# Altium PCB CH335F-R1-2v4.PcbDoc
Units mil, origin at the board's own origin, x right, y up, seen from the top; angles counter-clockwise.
Board outline 3110.24 x 866.14 mil, 2 copper layers (Top Layer, Bottom Layer); 18 components, 20 nets, 111 pads, 301 vias.
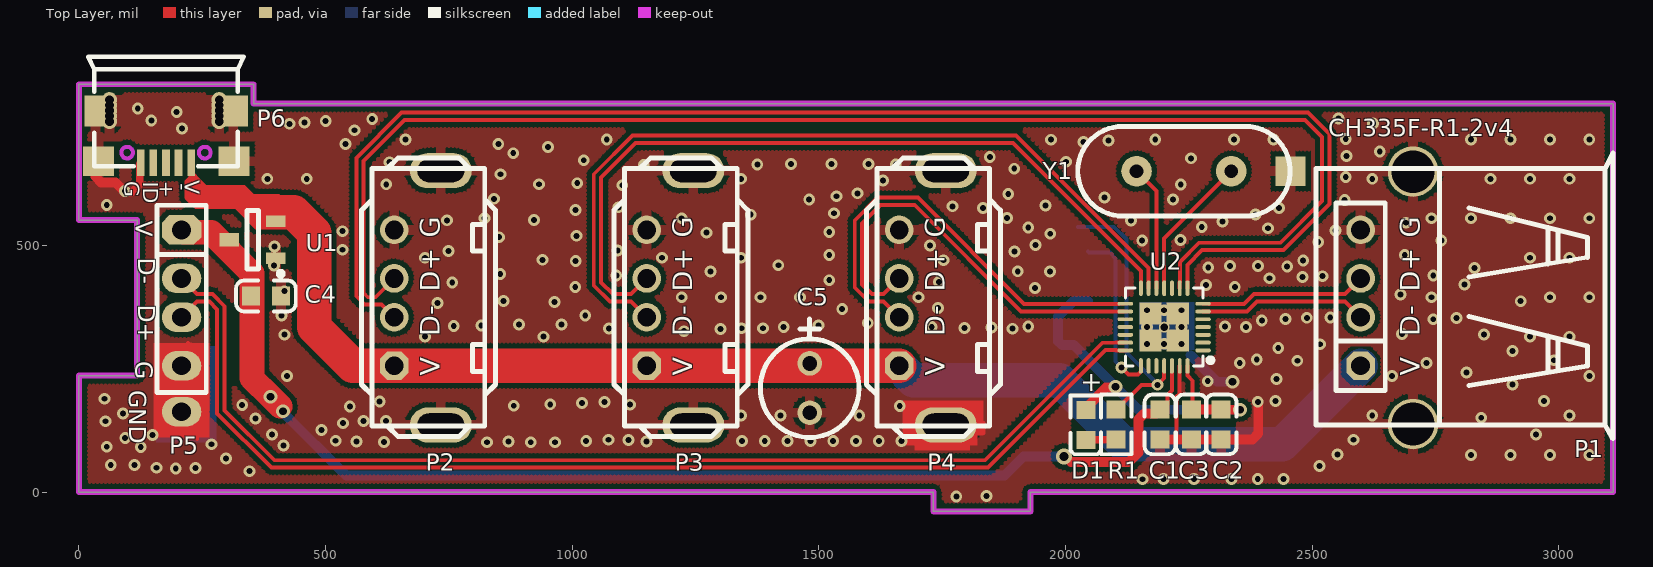
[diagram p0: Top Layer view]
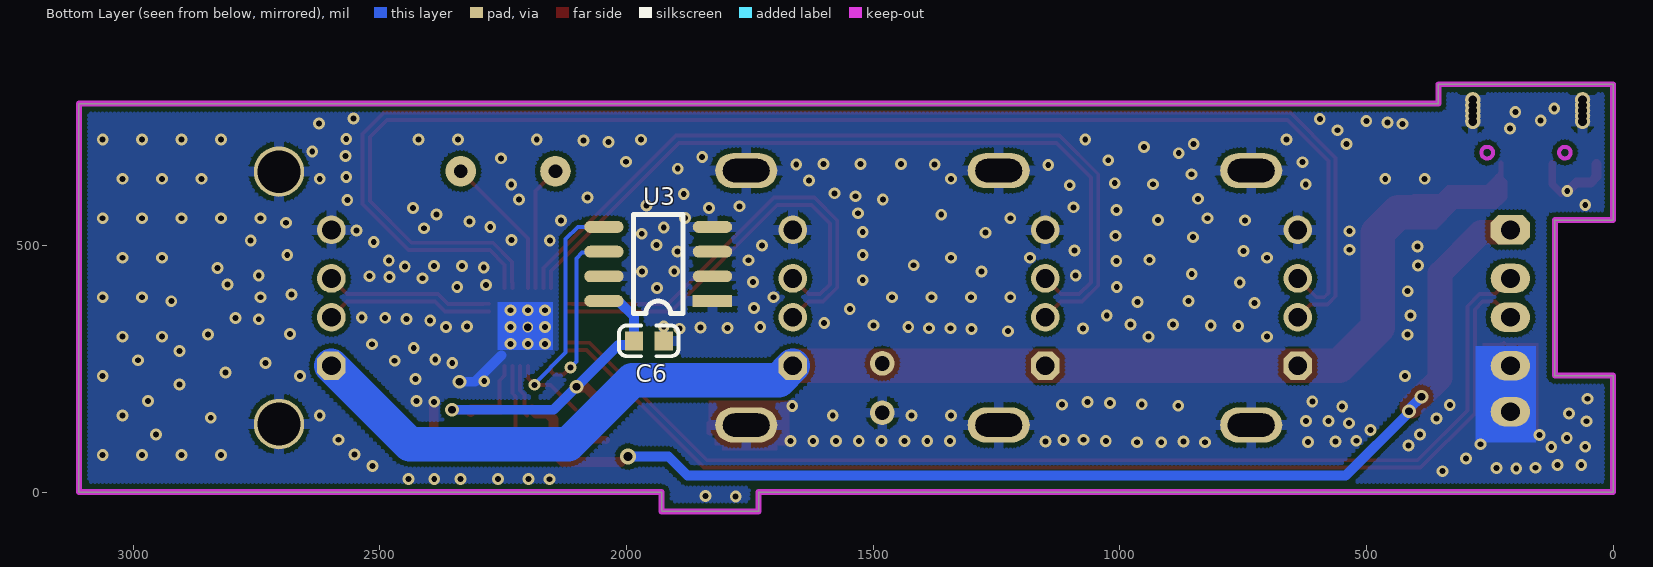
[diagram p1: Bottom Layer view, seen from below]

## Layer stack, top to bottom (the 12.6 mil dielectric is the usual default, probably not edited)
Top Solder: solder mask 0.4, Solder Resist, Dk 3.5
Top Layer: signal copper 1.4
Dielectric 1: dielectric 12.6, FR-4, Dk 4.8
Bottom Layer: signal copper 1.4
Bottom Solder: solder mask 0.4, Solder Resist, Dk 3.5

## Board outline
0,0 0,236.22 118.11,236.22 118.11,551.18 0,551.18 0,826.77 354.33,826.77 354.33,787.4 3110.24,787.4 3110.24,0 1929.13,0 1929.13,-39.37 1732.28,-39.37 1732.28,0

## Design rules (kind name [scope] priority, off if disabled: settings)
Clearance Clearance_1 [InPolygon] p1: gap=10 ignorepadtopadclearanceinfootprint=FALSE
Clearance [All] p2: gap=6 ignorepadtopadclearanceinfootprint=FALSE except(8: Arc-Via Track-Via SMDPad-Via THPad-Via Via-Via Via-Fill Via-Poly Via-Region Via-Hole)
ComponentClearance [All] p1 off: gap=10 collisioncheckmode=3 verticalgap=10 showdistances=FALSE
DiffPairsRouting [All] p1: maxlimit=10 minlimit=7 mostfreqgap=8 toplayer_minwidth=6 toplayer_maxwidth=15 toplayer_prefwidth=8 bottomlayer_minwidth=6 bottomlayer_maxwidth=15 bottomlayer_prefwidth=8 maxuncoupledlength=500
MinimumSolderMaskSliver [All] p1 off: minsoldermaskwidth=10
PolygonConnect PolygonConnect_1 [IsVia] p1: connectstyle=Direct reliefconductorwidth=10 reliefentries=4 polygonreliefangle="90 Angle" airgapwidth=10
PolygonConnect [All] p2: connectstyle=Relief reliefconductorwidth=20 reliefentries=4 polygonreliefangle="90 Angle" airgapwidth=10
RoutingVias [All] p1: holewidth=16 width=28 viastyle="Through Hole" minholewidth=12 minwidth=24 maxholewidth=28 maxwidth=50
SilkToSilkClearance [All] p1 off: silktosilkclearance=10
SilkToSolderMaskClearance [IsPad] p1 off: minsilkscreentomaskgap=10 clearancetoexposedcopper=TRUE
SolderMaskExpansion [All] p1: expansion=4 istentingtop=FALSE
Width [All] p1: maxlimit=100 minlimit=6 preferedwidth=10
25 further rules are at their usual default settings.

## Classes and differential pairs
differential pair UD: +UD_p -UD_n
differential pair UD4: +UD4_p -UD4_n
differential pair UD3: +UD3_p -UD3_n
differential pair UD2: +UD2_p -UD2_n
differential pair UD1: +UD1_p -UD1_n

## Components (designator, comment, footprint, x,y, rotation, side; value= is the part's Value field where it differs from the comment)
C1 "1uF" 0603_C 2191.7,167.36 r270 top
C2 "10uF" 0603_C 2315.79,167.36 r270 top
C3 "0.1uF" 0603_C 2255.33,167.36 r270 top
C4 "10uF" 0603_C 349,397.5 r0 top
C5 "220uF" CD0.1 1481.53,260.82 r270 top
C6 "NC(1uF)" 0603_C 1924.53,306.51 r0 bottom
D1 "LED" 0603+ 2041.27,165.98 r270 top
P1 "USB" USBAF#1 2598.25,255.91 r90 top
P2 "USB" USB2.0-A-F-TH_4P-V_13.7mm 639.21,255.91 r180 top
P3 "USB" USB2.0-A-F-TH_4P-V_13.7mm 1151.02,255.91 r180 top
P4 "USB" USB2.0-A-F-TH_4P-V_13.7mm 1662.83,255.91 r180 top
P5 "USB" USBAF#2 208.21,531.5 r270 top
P6 "PowerSupply" USBMICROB-02-GXPX-A1T2 227.66,667.45 r180 top
R1 "1K" 0603_R 2102.92,137.04 r270 top
U1 "CH213K" SOT-23-3 399.31,474.12 r90 top
U2 "CH335F" QFN28_4X4 2200.14,334.5 r90 top
U3 "NC(24C02)" SOIC-8_150mil 1825.82,387.4 r90 bottom
Y1 "12M" XT_AT49 2336.23,650.53 r90 top

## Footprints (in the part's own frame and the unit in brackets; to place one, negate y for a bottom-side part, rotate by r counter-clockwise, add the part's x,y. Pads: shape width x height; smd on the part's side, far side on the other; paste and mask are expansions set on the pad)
0603+ [mm]
  rect 0.93x0.98 smd: 1(0,0) 2(1.54,0)
  silkscreen extent -0.76,-0.79 2.27,0.79
0603_C [mm]
  rect 0.93x0.98 smd: 1(0,0) 2(1.54,0)
  silkscreen extent -0.76,-0.79 2.31,0.79
0603_R [mm]
  rect 0.93x0.98 smd: 1(-0.77,0) 2(0.77,0)
  silkscreen extent -1.53,-0.79 1.54,0.79
CD0.1 [mil]
  round 50 hole 30: 1(0,0) 2(100,0)
  silkscreen extent -90,-100 150,100
QFN28_4X4 [mm]
  rect 1.143x1.143 smd mask+0: 0(-0.699,-0.699) 0(-0.699,0.698) 0(0.699,-0.699) 0(0.699,0.698)
  round 0.559 hole 0.381 mask+0.051: 0(0,0)
  oval 0.2x0.8 smd mask+0.051: 1(-1.2,-2) 2(-0.8,-2) 3(-0.4,-2) 4(0,-2) 5(0.4,-2) 6(0.8,-2) 7(1.2,-2) 15(1.2,2) 16(0.8,2) 17(0.4,2) 18(0,2) 19(-0.4,2) 20(-0.8,2) 21(-1.2,2)
  oval 0.8x0.2 smd mask+0.051: 8(2,-1.2) 9(2,-0.8) 10(2,-0.4) 11(2,0) 12(2,0.4) 13(2,0.8) 14(2,1.2) 22(-2,1.2) 23(-2,0.8) 24(-2,0.4) 25(-2,0) 26(-2,-0.4) 27(-2,-0.8) 28(-2,-1.2)
  silkscreen extent -2,-2.51 2,2
SOIC-8_150mil [mil]
  rect 24x80 smd: 1(0,0)
  oval 24x80 smd: 2(50,0) 3(100,0) 4(150,0) 5(150,220) 6(100,220) 7(50,220) 8(0,220)
  silkscreen extent -25,60 175,160
SOT-23-3 [mm] "SOT-23-3"
  rect 0.6x1 smd: 1(0,0) 2(1.9,0)
  rect 0.7x1 smd: 3(0.95,2.4)
  silkscreen extent -0.93,-0.38 2.45,1.49
USB2.0-A-F-TH_4P-V_13.7mm [mm]
  oval 3.2x1.8 hole 1.2 slot 2.4 at 0 deg: 0(-2.4,3.05) 0(-2.4,-10.05)
  oct 1.473x1.473 hole 0.965: 1(0,0)
  round 1.473 hole 0.965: 2(0,-2.5) 3(0,-4.5) 4(0,-7)
  silkscreen extent -5.21,-10.71 1.69,3.65
USBAF#1 [mm]
  round 2.6 hole 2.2: 0(-3,-2.7) 0(10,-2.7)
  oct 1.473x1.473 hole 0.965: 1(0,0)
  round 1.473 hole 0.965: 2(2.5,0) 3(4.5,0) 4(7,0)
  silkscreen extent -3.75,-12.99 10.95,2.29
USBAF#2 [mm]
  oct 1.524x2.032 hole 0.965: 1(0,0)
  oval 1.524x2.032 hole 0.965: 2(2.5,0) 3(4.5,0) 4(7,0)
  silkscreen extent -1.27,-1.27 8.38,1.27
USBMICROB-02-GXPX-A1T2 [mm]
  rect 1.6x1.5 smd: 0(-2.203,-0.083) 0(4.769,-0.083)
  rect 1.5x1.6 smd: 0(-2.167,-2.675)
  round 0.8 hole 0.45: 0(-1.442,-2.134) 0(-1.442,-3.243) 0(-1.442,-2.966) 0(-1.442,-2.689) 0(-1.442,-2.411) 0(4.208,-2.689) 0(4.208,-2.411) 0(4.208,-2.134) 0(4.208,-3.243) 0(4.208,-2.966)
  rect 1.1x1.6 smd: 0(4.933,-2.675)
  rect 0.4x1.35 smd mask+0.051: 1(0,0) 2(0.65,0) 3(1.3,0) 4(1.95,0) 5(2.6,0)
  Keep-Out Layer circle w0.203: c3.3,-0.525 r0.3
  Keep-Out Layer circle w0.203: c-0.7,-0.525 r0.3
  silkscreen extent -2.7,-5.46 5.3,0.17
XT_AT49 [mil]
  rect 60x60 smd: 0(0.03,-119.99)
  round 62 hole 28: 1(0,0) 2(0,192.13)
  silkscreen extent -91,-119 91,311

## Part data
C1 C2 C3 C4 C5 C6: library part CAP, "Capacitor"
D1: "Typical INFRARED GaAs LED"
P1 P2 P3 P4 P5: "USB Port"
P6: library part MicroUSB, "MicroUSB Port"
R1: library part RES
U1: "Ideal Diode 5V*1A"
U2: "4 ports High-Speed USB MTT Hub with 4 over current detect & power control"
U3: library part 24C01
Y1: library part XTAL, "Crystal Oscillator"

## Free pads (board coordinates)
  oval 80x60 hole 38: ""(208.21,162.81)

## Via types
v1: diameter 24, hole 12, Top Layer to Bottom Layer, tented both sides, 295 vias
v2: diameter 28, hole 16, Top Layer to Bottom Layer, tented both sides, 5 vias
v3: diameter 32, hole 18, Top Layer to Bottom Layer, tented both sides, 1 vias

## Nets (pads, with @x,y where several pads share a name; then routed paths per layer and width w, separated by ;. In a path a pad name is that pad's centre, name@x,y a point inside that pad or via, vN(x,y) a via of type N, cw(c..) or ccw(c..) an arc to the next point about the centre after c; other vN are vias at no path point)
3V3: C2.1 C3.1 C6.2 D1.1 U2.28 U3.8 | length 826.5
  Top Layer w8: U2.28 2247.39,235.98 2257.75,225.62 C3.1@2257.75,167.36
  Top Layer w20: D1.1 2042.26,165.98 2050.57,174.28 2050.57,179.46 2065.22,194.12 2065.22,195.06 2082.1,211.95 2099.74,211.95 v2(2101.27,213.48) ; C3.1 2257.75,167.36 C2.1 ; C2.1@2315.79,162.1 2320.59,166.9 v2(2353.6,166.9)
  Bottom Layer w20: C6.2@1985.16,305.53 C6.2@1985.16,306.39 ; U3.8 2016.74,387.4 1985.16,355.82 C6.2 C6.2@1985.16,306.39 ; v2(2353.6,166.9) 2147.92,166.9 2016.75,298.08 1993.46,298.08 C6.2@1985.16,306.39
5V: C1.1 C4.1 P5.1 U1.3 U2.26 | length 2567.1
  Top Layer w8: C1.1@2201.91,155.57 2206.99,160.65 2206.99,196.73 2215.89,205.63 U2.26
  Top Layer w20: v2(413.82,163.9) 416.27,163.9 v2@422.95,170.59 ; v3(1997,72) 2000.25,72 2011.02,61.23 2128.8,61.23 2148.07,80.5 2148.07,147.53 2159.78,159.24 2183.59,159.24 C1.1
  Top Layer w50: P5.1 212.86,526.85 267.86,526.85 350.86,443.86 350.86,231.09 v2(388.71,193.23) v2@407.93,174.01
  Bottom Layer w20: v2(388.71,193.23) 413.82,168.12 v2(413.82,163.9) 413.82,161.47 541.94,33.35 1876.39,33.35 1915.04,72 v3(1997,72)
GND: C1.2 C2.2 C3.2 C4.2 C5.2 C6.1 P1.0 P1.4 P2.0 P2.4 P3.0 P3.4 P4.0 P4.4 P5.4 P6.0 P6.5 pad. U1.1 U2.0 U2.27 U3.1 U3.2 U3.3 U3.4 U3.7 Y1.0 | length 1560
  Top Layer w8: 220.81,208.41 220.81,302.53 ; 222,112.53 222,206.65 ; 225,112.53 225,206.65 ; 227.09,204.87 227.09,299 ; 230,111.08 230,205.21 ; 233,204.17 233,298.3 ; 234,111.08 234,205.21 ; 240,107.99 240,295.21 ; 1834.11,119.74 1834.11,140.29 ; 2225.32,106.73 2225.32,193.95 2231.64,200.27 U2.27
  Top Layer w15: 104.84,605.5 123.71,624.36 P6.5@123.71,665.85
  Top Layer w20: P6.0@33.46,665 33.46,639.41 45.12,627.76 74.35,627.76 91.94,610.17 v1(93.02,610.17) ; C1.2 2225.32,106.73 C3.2 C2.2 2379.08,106.73 2390.79,118.44 2390.79,181.02 2389.91,181.9 v1(2389.91,182.98)
  Bottom Layer w20: 2253.43,277.44 2307.24,223.63 v2(2338.61,223.63)
  other v1: 1778.73,-8.71 1840.22,-8.03 2156.11,26 2198.52,26.3 2260.61,26.3 2336.5,26.3 2389.86,26.3 2441.72,26.3 345.77,42.29 196.36,47.86 157.58,49.29 236.59,48.81 2514.7,52.91 64.67,55.04 112.56,54.56 298,68.06 2822,75 2902,75 2982,75 3062,75 2551.51,75.81 125.49,91.43 56.53,91.91 414.85,94.07 269.09,96.97 618.87,101.5 827.57,100.98 916.07,100.98 965.42,100.98 563.05,102.8 870.97,102.68 1150.93,102.68 1344.12,103.19 1390.38,103.19 1436.63,103.19 1482.89,103.19 1529.14,103.19 1575.4,103.19 1621.65,103.19 1667.91,103.19 520.64,104.1 1028.39,103.53 1114.34,105.23 1073.49,106.08 2584.23,106.08 93.89,109.63 149.43,115.38 391.59,116.41 2953.66,116.98 491.94,125.77 535.35,139.58 54.14,143.63 576.89,143.91 622.77,143.91 357.77,148.98 2842.89,150.73 1342,155 1422,155 1582,155 2622,155 3022,155 89.58,159.43 549.2,173.34 1664.05,174.13 881.63,174.96 331.09,176.59 1117.55,177.16 955.63,177.89 1020.11,180.82 1065.53,182.28 609.78,183.72 2970.04,184.47 2426.11,184.58 51.74,189.12 2906.47,218.22 2288.39,224.78 2427.67,229.49 422,235 2662,235 3062,235 2813.04,242.58 2353.32,261.95 2732.05,261.79 2470.02,266.19 2990.27,267.24 2387.72,269 2906.47,285.71 2431.43,292.07 2516.13,299.6 2165.14,300.5 2200.14,300.5 2235.14,300.5 702,315 942,315 2942,315 3022,315 417.14,319.02 2848.67,319.45 2681.97,320.55 1226.76,326.1 1300.83,330.59 1892.62,331.18 1074.39,331.87 1343.48,332.09 1386.87,332.09 1795.48,332.6 1428.77,334.33 1729.02,334.29 1849.9,333.65 2366.03,334.42 2165.14,334.5 2235.14,334.5 2323.68,335.36 1924.53,335.8 760.01,336.88 815.69,337.61 1499.1,338.08 891.89,339.81 978.34,339.81 1599.31,342.91 2398.02,347.59 2745.54,350.41 2446.02,350.89 2489.31,353.24 2792.74,353.2 2536.83,353.71 410.85,357.83 1026.45,358.11 2165.14,368.5 2200.14,368.5 2235.14,368.5 1547.41,370.82 1741.77,372.97 727.04,383.04 964.42,385.23 861.12,387.43 2922.84,386.94 1222,395 1302,395 1382,395 1462,395 1702,395 2742,395 2982,395 3062,395 2679.08,400.49 416.43,407.17 1938.12,413.6 1006.25,415.39 2343.32,415.81 2284.92,419.52 2809.11,420.69 756.97,424.97 1743.53,425.98 1521.18,429.51 2413.32,433.43 2480.53,435.75 2521.32,437.6 1089.52,439.16 2745.54,439.02 854.15,442.08 1280.14,447.3 1968.35,447.08 1903.25,447.54 2829.34,454.43 2289.55,455.22 2333.59,458 2390.61,458 2449.47,457.53 395.86,459.26 1417.86,459.82 1007.16,468.13 2481.92,469.12 1752.65,469.86 939.67,470.84 702,475 1182,475 1342,475 2942,475 3022,475 2687.75,480.44 1521.18,480.68 1896.74,487.53 749.2,488.72 1092.19,489.51 534.29,491.3 396.6,497.91 1725.48,499.88 1939.05,500.55 2512.51,507.13 2155.54,509.82 2761.91,510.3 2233.08,510.98 851.82,516.71 1009,519.49 1969.16,523.57 1272.17,525.84 1521.18,527.32 534.29,528.86 2547.29,530.47 2410.57,534.75 1924.64,536.35 2276.34,537.4 2690.64,545.94 2318.33,548.57 746.09,550.91 2133.17,550.63 922.56,551.69 822,555 1222,555 1881.66,555.45 2742,555 2822,555 2902,555 2982,555 3062,555 1362.09,562.26 2385.45,562.67 1530.66,565.24 1006.71,571.47 1832.96,575.82 2433.11,576.09 1093.71,577.24 1770.67,579.29 1959.21,580.79 56.52,582.14 2566.1,591.77 1480.46,592.99 2217.74,593.2 841.71,594.45 2078.97,596.86 1535.62,599.64 1883.96,604.43 1578.21,605.62 1101.53,621.94 623.08,623.85 932.67,623.99 2233.75,623.56 1010.25,626.12 1629.84,631.7 382,635 462,635 1342,635 2622,635 2862,635 2942,635 3022,635 2568.15,638.86 854.93,644.21 1896.17,655.57 1145.12,662.73 1375.3,663.89 1655.97,663.89 1443.81,664.72 1525.54,664.72 1600.66,664.72 629.57,668.76 2001.3,669.58 1023.41,672.66 2254.17,676.55 1846.66,679.25 2569.68,681.35 880.58,686.96 2637.09,690.68 951.33,699.4 540.34,705.78 850.26,705.62 2036.88,709.51 2087.31,712.53 1970.83,714.32 662,715 1070.19,714.85 2182,715 2342,715 2422,715 2822,715 2902,715 2982,715 3062,715 2568.15,715.65 559.03,733.42 209.17,737.14 426.68,746.52 2623.79,747.43 457.39,749.48 500.31,752.44 146.87,753.14 594.56,756.21 2553.53,757.46 198.29,770.28 119.32,777.75
NetD1_2: D1.2 R1.2 | length 62.2
  Top Layer w15: D1.2 2041.96,106.04 2102.23,106.04 R1.2
RST: U2.17
SCL: U2.22 U3.6 | length 350.7
  Top Layer w8: v1@2111.21,254.86 2127.84,238.23 2147.05,238.23 2152.9,244.08 U2.22
  Bottom Layer w8: U3.6 2047.63,485.58 2089.95,485.58 2101.81,473.72 2101.81,264.87 2113.55,253.13 v1(2113.55,252.19)
SDA: R1.1 U2.25 U3.5 | length 578.6
  Top Layer w8: R1.1 2103.91,167.36 2153.95,217.4 v1(2186.86,217.4) 2200.14,230.68 U2.25
  Bottom Layer w8: U3.5@2025.13,537.4 2098.73,537.4 2123.43,512.69 2123.43,282.72 2186.86,219.29 v1(2186.86,217.4)
UD1_n: P1.2 U2.6 | length 340.9
  Top Layer w8: U2.6 2290.57,366 2290.94,366.37 2368.17,366.37 2388,386.2 2566.38,386.2 P1.2
UD1_p: P1.3 U2.7 | length 340.9
  Top Layer w8: U2.7 2290.57,381.75 2290.94,381.37 2361.96,381.37 2381.79,401.2 2566.38,401.2 P1.3
UD2_n: P2.2 U2.8 | length 2932.6
  Top Layer w8: P2.2 639.1,354.33 613.48,379.95 579.38,379.95 562.42,396.91 562.42,677.61 654.21,769.4 2491.57,769.4 2535.17,725.8 2535.17,583.83 2441.75,490.41 2276.83,490.41 2247.01,460.59 2247.01,425.3 2247.39,424.93 U2.8
UD2_p: P2.3 U2.9 | length 2863.3
  Top Layer w8: P2.3 601.09,394.95 585.59,394.95 577.42,403.13 577.42,671.4 660.42,754.4 2485.36,754.4 2520.17,719.59 2520.17,590.05 2435.54,505.41 2270.62,505.41 2232.01,466.81 2232.01,425.3 2231.64,424.93 U2.9
UD3_n: P3.2 U2.13 | length 1668.6
  Top Layer w8: P3.2 1119.15,386.2 1076.47,386.2 1043.71,418.96 1043.71,644.31 1121.89,722.5 1899.96,722.5 2168.27,454.18 2168.27,425.3 2168.65,424.93 U2.13
UD3_p: P3.3 U2.14 | length 1594.1
  Top Layer w8: P3.3 1119.15,401.2 1082.69,401.2 1058.71,425.18 1058.71,638.1 1128.11,707.5 1893.75,707.5 2153.27,447.97 2153.27,425.3 2152.9,424.93 U2.14
UD4_n: P4.2 U2.15 | length 907.9
  Top Layer w8: P4.2 1630.96,386.2 1601.41,386.2 1572.91,414.7 1572.91,550.65 1619.08,596.82 1700.64,596.82 1916.09,381.37 2109.34,381.37 2109.72,381.75 U2.15
UD4_p: P4.3 U2.16 | length 858.2
  Top Layer w8: P4.3 1630.96,401.2 1607.62,401.2 1587.91,420.92 1587.91,544.44 1625.29,581.82 1694.43,581.82 1909.87,366.37 2109.34,366.37 2109.72,366 U2.16
UD_n: P5.2 U2.20 | length 2288.9
  Top Layer w8: P5.2 208.21,432.1 239.11,401.2 270.83,401.2 295.32,376.71 295.32,165.72 396.59,64.44 1837.19,64.44 2075.38,302.63 2102.43,302.63 2102.74,302.95 2121.34,302.95 U2.20
UD_p: P5.3 U2.21 | length 2288.9
  Top Layer w8: P5.3 208.21,355.3 239.11,386.2 264.62,386.2 280.32,370.5 280.32,159.5 390.38,49.44 1843.4,49.44 2081.6,287.63 2102.43,287.63 2102.74,287.32 2121.34,287.32 U2.21
VBUS: C5.1 P1.1 P2.1 P3.1 P4.1 P6.1 U1.2 | length 3173.9
  Top Layer w10: 247.13,591.38 252.13,591.38 ; 252.85,603.63 251.45,605.02 ; 252.85,608.63 252.85,605.02 ; 254.37,584.14 259.37,584.14 ; 267.21,605.02 262.21,605.02 ; 276.12,579.63 263.88,579.63 ; 219.15,602.21 241.73,579.63 ; 219.15,602.21 219.15,629.22 226.76,636.83 226.76,666.54 P6.1 P6.1@227.66,646.78 ; 219.15,602.21 219.15,597.21 236.73,579.63 241.73,579.63 ; 227.66,615.85 227.66,619.83 ; 227.66,615.85 227.66,604.47 252.5,579.63 ; 227.66,615.85 238.49,605.02 ; 227.66,619.83 227.66,628.81 ; 227.66,619.83 242.47,605.02 ; 227.66,628.81 251.45,605.02 ; 227.66,628.81 P6.1@227.66,646.78 ; P6.1@227.66,646.78 234.14,640.3 ; 234.14,640.3 274.41,600.02 267.21,600.02 ; 234.14,640.3 234.14,633.09 262.21,605.02 ; 238.49,605.02 242.47,605.02 ; 238.49,605.02 252.13,591.38 ; 241.73,579.63 252.5,579.63 ; 242.47,605.02 251.45,605.02 ; 242.47,605.02 247.47,600.02 257.85,600.02 ; 251.45,605.02 252.85,605.02 ; 252.13,591.38 266.49,591.38 257.85,600.02 ; 252.13,591.38 259.37,584.14 ; 252.5,579.63 263.88,579.63 ; 252.85,605.02 262.21,605.02 ; 252.85,605.02 257.85,600.02 ; 257.85,600.02 267.21,600.02 ; 259.37,584.14 263.88,579.63 ; 262.21,605.02 267.21,600.02
  Top Layer w70: 402.72,567.41 435.25,567.41 476.84,525.82 476.84,334.52 555.45,255.91 P2.1 P3.1 P4.1
  Bottom Layer w70: P4.1 1691.8,226.94 1988.46,226.94 2118.1,97.31 2439.65,97.31 P1.1
XI: U2.11 Y1.1 | length 293.7
  Top Layer w8: U2.11 2200.14,514.44 Y1.1@2329.1,643.4
  Top Layer w10: Y1.1@2329.1,643.4 Y1.1
XO: U2.12 Y1.2 | length 254
  Top Layer w8: Y1.2 2184.4,610.24 U2.12
pads on no net: P6.2 P6.3 P6.4 U2.1 U2.2 U2.3 U2.4 U2.5 U2.10 U2.18 U2.19 U2.23 U2.24

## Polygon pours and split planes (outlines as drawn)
GND on Bottom Layer "GND" (hatched 90Degree grid 8 track 8, remove dead copper, pour order 1): 0,826.77 0,551.18 118.11,551.18 118.11,236.22 0,236.22 0,0 1732.28,0 1732.28,-39.37 1929.13,-39.37 1929.13,0 3110.24,0 3110.24,787.4 354.33,787.4 354.33,826.77
GND on Top Layer "GND" (hatched 90Degree grid 8 track 8, remove dead copper, pour order 0): 0,826.77 0,551.18 118.11,551.18 118.11,236.22 0,236.22 0,0 1732.28,0 1732.28,-39.37 1929.13,-39.37 1929.13,0 3110.24,0 3110.24,787.4 354.33,787.4 354.33,826.77

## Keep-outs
Keep-Out Layer:
  the board outline again, w12

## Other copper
Top Layer:
  rectangle net GND: 1694,84.44 1806,101.7
  rectangle net GND: 1668.7,94.34 1822.2,119.42
  rectangle net GND: 1669.7,115 1834.11,185.26
  rectangle net GND: 151.31,111.08 265.24,302.38
  region net VBUS: 219.15,629.22 219.15,590.62 235.52,574.25 316.63,574.25 357.93,532.96 402.24,532.96 415.62,546.34 415.62,595.01 406.58,604.05 354.79,604.05 336.36,622.47 257.64,622.47 249.93,630.18
Bottom Layer:
  rectangle net GND: 2148.87,287.82 2261.35,384.85
  rectangle net GND: 156.56,100.86 278.7,295.9

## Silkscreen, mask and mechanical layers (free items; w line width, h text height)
Top Overlay:
  text "CH335F-R1-2v4" at 2532.39,721.18 h35
  text "GND" at 102.23,206.83 h35 r270
Mechanical 1:
  lines w10: 0,0 0,236.22 118.11,236.22 118.11,551.18 0,551.18 0,787.4 0,826.77 354.33,826.77 354.33,787.4 3110.24,787.4 3110.24,0 1929.13,0 1929.13,-39.37 1732.28,-39.37 1732.28,0 0,0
